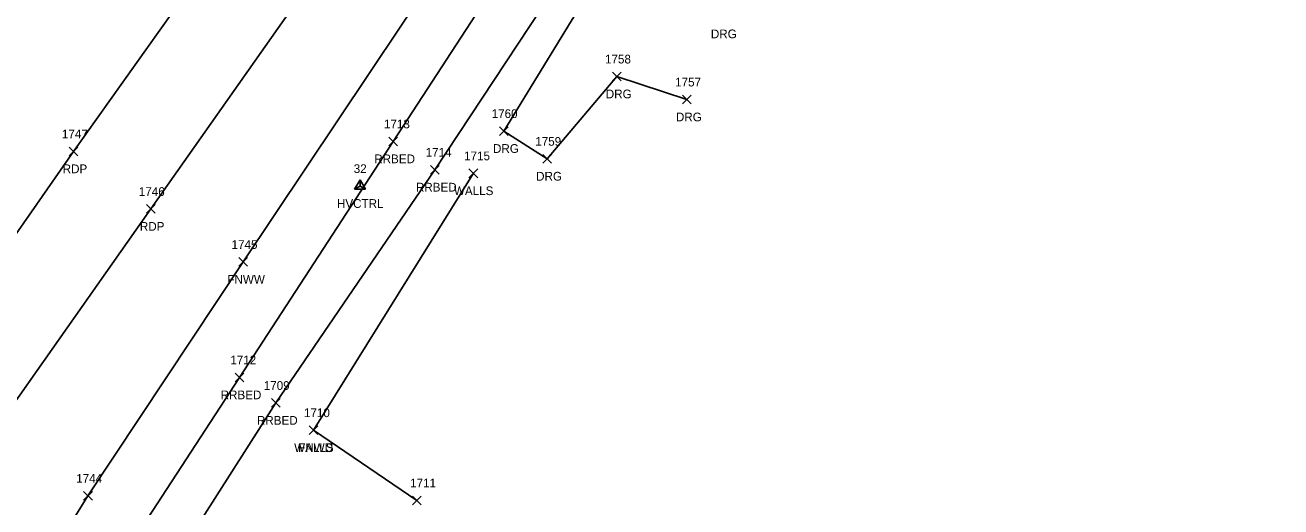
# Model space of a CAD drawing. Extents: x 1508122 to 1515053, y 865012 to 875267.
# Drawn here: x 1511441.4 to 1511729.8, y 870102.7 to 870213.2 of the extents above; entities that cross this region are included whole.
import ezdxf

# ---------------------------------------------------------------- set-up
doc = ezdxf.new("R2010")
doc.units = 0
for name, color, linetype in [('C_A', 7, 'Continuous'), ('C_I', 7, 'Continuous'), ('CPSM', 7, 'Continuous'), ('L_A', 7, 'Continuous'), ('L_I', 7, 'Continuous'), ('L_TIC', 7, 'Continuous'), ('LFNC', 7, 'Continuous'), ('LWS', 7, 'Continuous'), ('P_A', 7, 'Continuous'), ('P_I', 7, 'Continuous'), ('P_TIC', 7, 'Continuous'), ('PET', 7, 'Continuous'), ('R_A', 7, 'Continuous'), ('R_I', 7, 'Continuous'), ('R_TIC', 7, 'Continuous'), ('RDG', 7, 'Continuous'), ('RRB', 7, 'Continuous')]:
    doc.layers.add(name, color=color, linetype=linetype)

msp = doc.modelspace()

# ---------------------------------------------------------------- linework, layer by layer
at = {"layer": 'CPSM'}
for p, q in [((1511517.1, 870175.53), (1511518.35, 870177.7)), ((1511519.6, 870175.53), (1511518.35, 870177.7)), ((1511518.35, 870176.26), (1511518.35, 870177.7)), ((1511517.1, 870175.53), (1511518.35, 870176.26)), ((1511517.1, 870175.53), (1511519.6, 870175.53)), ((1511518.35, 870176.26), (1511518.35, 870176.26)), ((1511518.35, 870176.26), (1511519.6, 870175.53))]:
    msp.add_line(p, q, dxfattribs=at)
at = {"layer": 'L_TIC'}
for points in [[(1511543.36, 870178.19), (1511545.36, 870180.19)], [(1511545.36, 870178.19), (1511543.36, 870180.19)], [(1511490.53, 870157.85), (1511492.53, 870159.85)], [(1511492.53, 870157.85), (1511490.53, 870159.85)], [(1511506.67, 870119.25), (1511508.67, 870121.25)], [(1511508.67, 870119.25), (1511506.67, 870121.25)], [(1511506.67, 870119.25), (1511508.67, 870121.25)], [(1511508.67, 870119.25), (1511506.67, 870121.25)], [(1511454.87, 870104.19), (1511456.87, 870106.19)], [(1511456.87, 870104.19), (1511454.87, 870106.19)], [(1511530.4, 870103.13), (1511532.4, 870105.13)], [(1511532.4, 870103.13), (1511530.4, 870105.13)]]:
    msp.add_lwpolyline(points, dxfattribs=at)
at = {"layer": 'LFNC'}
for points in [[(1511290.91, 869849.18), (1511327.8, 869904.4), (1511394.98, 870009.98), (1511425.13, 870055.54), (1511455.87, 870105.19), (1511491.53, 870158.85), (1511535.01, 870223.89), (1511575.2, 870287.48), (1511608.77, 870338.28), (1511623.7, 870361.63)], [(1511507.67, 870120.25), (1511531.4, 870104.13)]]:
    msp.add_lwpolyline(points, dxfattribs=at)
at = {"layer": 'LWS'}
msp.add_lwpolyline([(1511507.67, 870120.25), (1511544.36, 870179.19)], dxfattribs=at)
at = {"layer": 'P_TIC'}
for points in [[(1511451.57, 870183.22), (1511453.57, 870185.22)], [(1511453.57, 870183.22), (1511451.57, 870185.22)], [(1511469.29, 870170.01), (1511471.29, 870172.01)], [(1511471.29, 870170.01), (1511469.29, 870172.01)]]:
    msp.add_lwpolyline(points, dxfattribs=at)
at = {"layer": 'PET'}
for points in [[(1511383.61, 870084.12), (1511412.26, 870126.56), (1511452.57, 870184.22), (1511495.01, 870243.9), (1511536.43, 870301.66), (1511577.25, 870358.31), (1511604.57, 870395.61), (1511633.77, 870437), (1511660.33, 870476.14), (1511693.36, 870526.39), (1511725.02, 870575.36), (1511757.6, 870625.52), (1511818.4, 870716.85), (1511845.17, 870758.16), (1511876.46, 870805.52)], [(1511401.8, 870072.69), (1511429.85, 870113.63), (1511470.29, 870171.01), (1511511.87, 870230.12), (1511553.79, 870288.68), (1511595.89, 870346.86), (1511627.03, 870388.71), (1511652.98, 870425.11), (1511678.36, 870464.06), (1511711.38, 870514.06), (1511744.84, 870564.55), (1511778.97, 870616.56), (1511830.16, 870695.92), (1511863.87, 870746.26), (1511895.07, 870793.96)]]:
    msp.add_lwpolyline(points, dxfattribs=at)
at = {"layer": 'R_TIC'}
for points in [[(1511576.29, 870200.4), (1511578.29, 870202.4)], [(1511578.29, 870200.4), (1511576.29, 870202.4)], [(1511592.38, 870195.12), (1511594.38, 870197.12)], [(1511594.38, 870195.12), (1511592.38, 870197.12)], [(1511550.38, 870187.88), (1511552.38, 870189.88)], [(1511552.38, 870187.88), (1511550.38, 870189.88)], [(1511524.95, 870185.51), (1511526.95, 870187.51)], [(1511526.95, 870185.51), (1511524.95, 870187.51)], [(1511560.28, 870181.52), (1511562.28, 870183.52)], [(1511562.28, 870181.52), (1511560.28, 870183.52)], [(1511534.52, 870179.01), (1511536.52, 870181.01)], [(1511536.52, 870179.01), (1511534.52, 870181.01)], [(1511489.68, 870131.35), (1511491.68, 870133.35)], [(1511491.68, 870131.35), (1511489.68, 870133.35)], [(1511498.01, 870125.5), (1511500.01, 870127.5)], [(1511500.01, 870125.5), (1511498.01, 870127.5)]]:
    msp.add_lwpolyline(points, dxfattribs=at)
at = {"layer": 'RDG'}
msp.add_lwpolyline([(1511593.38, 870196.12), (1511577.29, 870201.4), (1511561.28, 870182.52), (1511551.38, 870188.88), (1511582.31, 870239.44), (1511605.49, 870278.8), (1511623.41, 870306.97), (1511646.57, 870339.01), (1511650.01, 870353.39), (1511649.82, 870375.22), (1511644.95, 870384.04), (1511635.16, 870387.37), (1511627.03, 870388.71)], dxfattribs=at)
at = {"layer": 'RRB'}
for points in [[(1511436.1, 870048.65), (1511490.68, 870132.35), (1511525.95, 870186.51), (1511566.07, 870248.05), (1511610.28, 870315.1), (1511649.82, 870375.22), (1511670.06, 870409.5), (1511721.74, 870485.89), (1511765, 870552.19), (1511815.5, 870626.59), (1511852.37, 870681.17), (1511885.93, 870729.88), (1511937.25, 870806.65), (1511989.72, 870883.94), (1512013.79, 870920.57), (1512083.27, 871021.96), (1512129.35, 871090.14), (1512163.74, 871140.81), (1512188.75, 871177.43), (1512243.74, 871258.31), (1512286.31, 871321.24), (1512333.89, 871390.89), (1512361.47, 871430.92), (1512395.79, 871481.56)], [(1511445.67, 870042.93), (1511499.01, 870126.5), (1511535.52, 870180.01), (1511576.3, 870241.79), (1511620.47, 870308.47), (1511650.01, 870353.39), (1511678.48, 870398.64), (1511696.26, 870426.71), (1511730.11, 870478.59), (1511774.8, 870546.45), (1511824.54, 870619.21), (1511862.36, 870674.46), (1511895.49, 870722.79), (1511947.32, 870799.15)]]:
    msp.add_lwpolyline(points, dxfattribs=at)

# ---------------------------------------------------------------- texts
at = {"layer": 'C_A'}
msp.add_text('HVCTRL', height=2, dxfattribs=at).set_placement((1511513.04, 870171.26))
at = {"layer": 'C_I'}
msp.add_text('32', height=2, dxfattribs=at).set_placement((1511516.89, 870179.26))
at = {"layer": 'L_A'}
for s, p in [('WALLS', (1511539.9, 870174.19)), ('FNWW', (1511487.88, 870153.85)), ('WALLS', (1511503.21, 870115.25)), ('FNWD', (1511504.13, 870115.25))]:
    msp.add_text(s, height=2, dxfattribs=at).set_placement(p)
at = {"layer": 'L_I'}
for s, p in [('1715', (1511542.23, 870182.19)), ('1745', (1511488.84, 870161.85)), ('1710', (1511505.46, 870123.25)), ('1710', (1511505.46, 870123.25)), ('1744', (1511453.17, 870108.19)), ('1711', (1511529.84, 870107.13))]:
    msp.add_text(s, height=2, dxfattribs=at).set_placement(p)
at = {"layer": 'P_A'}
for p in [(1511450.06, 870179.22), (1511467.78, 870166.01)]:
    msp.add_text('RDP', height=2, dxfattribs=at).set_placement(p)
at = {"layer": 'P_I'}
for s, p in [('1747', (1511449.88, 870187.22)), ('1746', (1511467.54, 870174.01))]:
    msp.add_text(s, height=2, dxfattribs=at).set_placement(p)
at = {"layer": 'R_A'}
for s, p in [('DRG', (1511598.9, 870210.18)), ('DRG', (1511574.77, 870196.4)), ('DRG', (1511590.87, 870191.12)), ('DRG', (1511548.87, 870183.88)), ('RRBED', (1511521.6, 870181.51)), ('DRG', (1511558.77, 870177.52)), ('RRBED', (1511531.17, 870175.01)), ('RRBED', (1511486.33, 870127.35)), ('RRBED', (1511494.66, 870121.5))]:
    msp.add_text(s, height=2, dxfattribs=at).set_placement(p)
at = {"layer": 'R_I'}
for s, p in [('1758', (1511574.59, 870204.4)), ('1757', (1511590.69, 870199.12)), ('1713', (1511523.83, 870189.51)), ('1760', (1511548.56, 870191.88)), ('1759', (1511558.58, 870185.52)), ('1714', (1511533.4, 870183.01)), ('1712', (1511488.55, 870135.35)), ('1709', (1511496.23, 870129.5))]:
    msp.add_text(s, height=2, dxfattribs=at).set_placement(p)

doc.saveas('drawing.dxf')
